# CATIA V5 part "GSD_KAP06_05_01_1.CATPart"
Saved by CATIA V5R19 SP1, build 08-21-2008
Part number: GSD_CYLINDER_01
Definition: Beispielmodell für Funktion Zylinder / Cylinder.
Description: CATIA V5 Flächenmodellierung  Copyrigth (c) 2009 Maik Hertha IT Consultants
Bounding box of the stored display mesh (mm): x 20.002 to 79.998, y 20 to 80, z -30 to 105
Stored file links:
  \GSD_BUCH_UEBUNG\GSD_KAP06_05_01_01.CATPart
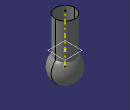
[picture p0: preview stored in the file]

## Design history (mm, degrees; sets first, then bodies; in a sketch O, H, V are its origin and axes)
Parameters
  Kugelradius = 30 mm
  Zylinderradius = 21 mm {= Kugelradius * 0.7}
AxisSystem1 "Absolute Axis System": origin (0, 0, 0), X (1, 0, 0), Y (0, 1, 0), Z (0, 0, 1)
Set1
  Plane1: type Offset, Offset 0, RefPlane XY plane of AxisSystem1
  Point1: type OnPlane, Support Plane1, Direction (1, 0, 0), H 50, V 50
  Line1: type PtDir, Direction Plane1, Start 0, End 105, RefPoint Point1
  Sphere1: Axis AxisSystem1, Angle1 -45, Angle3 0, Angle4 180, Center Point1, Radius 30 {= Kugelradius}
  Intersect1: ToIntersect1 Sphere1, ToIntersect2 Line1
  Plane2: type Normal, Curve Line1, RefPoint Intersect1
  Cylinder1: Length1 70, Length2 10, Center Intersect1, Radius 21 {= Zylinderradius}, Direction Plane2
Body1 (main body)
